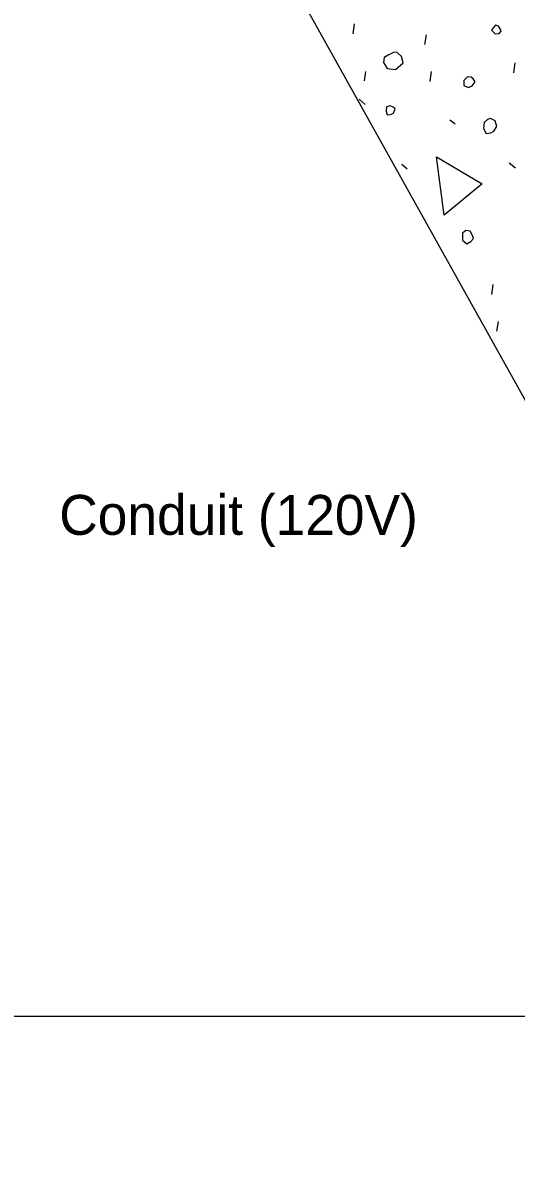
# Model space of a CAD drawing. Extents: x 112544 to 112597.1, y 111084 to 111107.1.
# Drawn here: x 112546.978 to 112548.848, y 111096.095 to 111100.441 of the extents above; entities that cross this region are included whole.
import ezdxf

# ---------------------------------------------------------------- set-up
doc = ezdxf.new("R2010")
doc.units = 0
for name, color, linetype in [('Dimension', 7, 'Continuous'), ('Miscellaneous', 7, 'Continuous'), ('SupstrConc', 7, 'Continuous'), ('TextStructures', 7, 'Continuous')]:
    doc.layers.add(name, color=color, linetype=linetype)

msp = doc.modelspace()

# ---------------------------------------------------------------- linework, layer by layer
at = {"layer": 'Dimension'}
msp.add_line((112546.25, 111096.6779), (112548.9157, 111096.6779), dxfattribs=at)
at = {"layer": 'Miscellaneous'}
for p, q in [((112548.2307, 111100.4002), (112548.2361, 111100.4379)), ((112548.5031, 111100.3593), (112548.5085, 111100.397)), ((112548.8396, 111100.2528), (112548.845, 111100.2905)), ((112548.2731, 111100.2227), (112548.2792, 111100.2579)), ((112548.5224, 111100.2196), (112548.5278, 111100.2573)), ((112548.2531, 111100.1526), (112548.2764, 111100.133)), ((112548.5976, 111100.0741), (112548.6173, 111100.0587)), ((112548.4149, 111099.9061), (112548.4352, 111099.8882)), ((112548.8223, 111099.9117), (112548.8457, 111099.8921)), ((112548.7567, 111099.4127), (112548.7622, 111099.4504)), ((112548.7761, 111099.273), (112548.7815, 111099.3107))]:
    msp.add_line(p, q, dxfattribs=at)
for points in [[(112548.755, 111100.4139), (112548.7692, 111100.3996), (112548.7844, 111100.4011), (112548.7921, 111100.4109), (112548.7908, 111100.4157), (112548.7821, 111100.4289), (112548.7705, 111100.4336), (112548.7628, 111100.4238), (112548.755, 111100.4139)], [(112548.3453, 111100.2912), (112548.3591, 111100.269), (112548.3913, 111100.2647), (112548.4205, 111100.2906), (112548.4141, 111100.3148), (112548.3968, 111100.3309), (112548.3841, 111100.3301), (112548.3637, 111100.3194), (112548.3481, 111100.31), (112548.3453, 111100.2912)], [(112548.6509, 111100.223), (112548.6506, 111100.2048), (112548.6683, 111100.1966), (112548.6822, 111100.2029), (112548.6934, 111100.2188), (112548.6854, 111100.2296), (112548.6786, 111100.2356), (112548.6676, 111100.2378), (112548.6628, 111100.2365), (112548.6509, 111100.223)], [(112548.3557, 111100.1076), (112548.3596, 111100.0931), (112548.3723, 111100.094), (112548.3837, 111100.0996), (112548.3895, 111100.1167), (112548.3827, 111100.1226), (112548.3711, 111100.1273), (112548.3567, 111100.1234), (112548.3557, 111100.1076)], [(112548.727, 111100.0648), (112548.7255, 111100.0411), (112548.7355, 111100.0231), (112548.7531, 111100.0252), (112548.7645, 111100.0308), (112548.7751, 111100.0492), (112548.7693, 111100.0709), (112548.7516, 111100.0791), (112548.7395, 111100.0759), (112548.727, 111100.0648)], [(112548.5752, 111099.7135), (112548.5472, 111099.9338), (112548.7193, 111099.8324), (112548.5752, 111099.7135)], [(112548.645, 111099.6365), (112548.6447, 111099.6183), (112548.6613, 111099.6046), (112548.6769, 111099.6139), (112548.6871, 111099.6244), (112548.6838, 111099.6365), (112548.6745, 111099.6521), (112548.658, 111099.6555), (112548.6455, 111099.6443), (112548.645, 111099.6365)]]:
    msp.add_lwpolyline(points, dxfattribs=at)
at = {"layer": 'SupstrConc'}
msp.add_line((112550.511, 111096.0946), (112547.0612, 111102.2767), dxfattribs=at)

# ---------------------------------------------------------------- texts
at = {"layer": 'TextStructures'}
msp.add_text('Conduit (120V)', height=0.1512, dxfattribs=at).set_placement((112547.1161, 111098.5017))

doc.saveas('drawing.dxf')
